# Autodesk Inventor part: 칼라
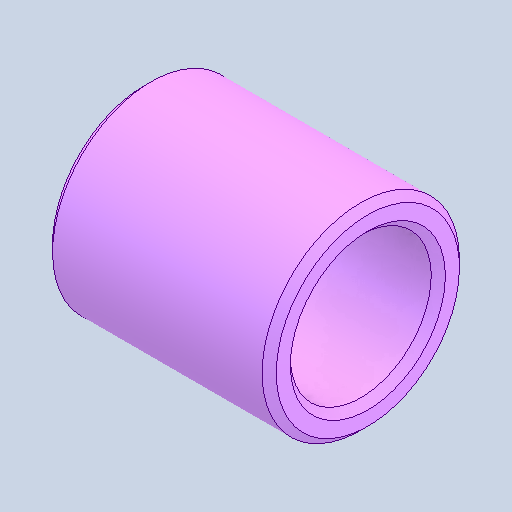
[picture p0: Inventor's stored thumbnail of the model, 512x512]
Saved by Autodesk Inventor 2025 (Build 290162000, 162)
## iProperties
Created: 2026-01
Part Number: 칼라
Material: 강철, 연강
Document SubType Name: Modeling
Designer: KDI
Density: 7.85 g/cm^3
Appearance: 기본값
Author: jhkim
Sending System: Autodesk Inventor 2026
Preprocessor: ST-DEVELOPER v20.1
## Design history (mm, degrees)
feature "솔리드1"
node "솔리드2"
